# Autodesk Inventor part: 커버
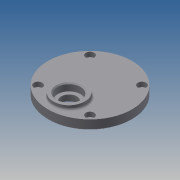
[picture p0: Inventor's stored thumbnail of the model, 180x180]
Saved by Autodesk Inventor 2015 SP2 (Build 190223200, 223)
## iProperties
Created: 2015-06
Part Number: 커버
Material: 일반
Document SubType Name: Modeling
Designer: AMC
Density: 1 g/cm^3
Appearance: 기본값
Author: AMC
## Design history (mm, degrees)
sketch "스케치1"
  geometry: C1 r 40 at (0, 0); 1 further point
  constraints: 1 centre point, 1 coincident
  dimensions: "d0" = 80 diameter of C1
extrude "돌출1" new body sketch "스케치1" distance "d1" = 9; taper "d2" = 0 deg
sketch "스케치2"
  geometry: C1 r 40 at (0, 0) reference; C2 r 15 at (0, -20); 1 further point
  constraints: 1 centre point, 1 vertical alignment
  dimensions: "d3" = 30 diameter of C2; "d4" = 20 distance of point (0, 0) C2.centre
extrude "돌출2" join sketch "스케치2" distance "d5" = 4; taper "d6" = 0 deg
sketch "스케치3"
  geometry: C1 r 14 at (0, -20); C2 r 14 at (0, 11); 1 further point
  constraints: 2 centre point, 2 vertical alignment
  dimensions: "d7" = 28 diameter of C1; "d8" = 20 distance of point (0, 0) C1.centre; "d9" = 11 distance of point (0, 0) C2.centre; "d10" = 28 diameter of C2
extrude "돌출3" join sketch "스케치3" distance "d11" = 3; taper "d12" = 0 deg
hole "구멍1" diameter "d15" = 15; stored, may be unused: countersink angle "d19" = 90 deg, drill point angle "d21" = 118 deg; dims "d13" = 10, "d14" = 10, "d16" = 6, "d17" = 22, "d18" = 7, "d20" = 8
node "작업 평면1"
sketch "스케치4"
  geometry: C1 r 14 at (0, 0) reference; C2 r 11 at (0, 0); 1 further point
  constraints: 1 centre point, 1 coincident
  dimensions: "d22" = 22 diameter of C2
extrude "돌출4" cut sketch "스케치4" distance "d23" = 7; taper "d24" = 0 deg
sketch "스케치5"
  geometry: C1 r 11 at (0, 0) reference; C2 r 9 at (0, 0); 1 further point
  constraints: 1 centre point, 1 coincident
  dimensions: "d25" = 18 diameter of C2
extrude "돌출5" cut sketch "스케치5" distance "d26" = 1; taper "d27" = 0 deg
fillet "모깎기1" dims "d28" = 1, "d29" = 0.3
chamfer "모따기1" distance "d30" = 1; stored, may be unused: second distance "d31" = 2, angle "d32" = 45 deg
sketch "스케치7"
  geometry: L1 (0, 0)-(-21.753, 0); 2 further points
  constraints: 2 end point, 1 coincident, 1 horizontal
  dimensions: "d35" = 45 deg dimension on L1.start L1.end point (-24.749, 24.749); "d36" = 35 distance of L1.start point (-24.749, 24.749)
hole "구멍2" sketch "스케치7" at (-24.749, 24.749) diameter "d37" = 4.5; stored, may be unused: countersink angle "d41" = 90 deg, drill point angle "d43" = 0 deg; dims "d38" = 6, "d39" = 8, "d40" = 4.4, "d42" = 8
fillet "모깎기2" dims "d47" = 2
chamfer "모따기2" distance "d48" = 1; stored, may be unused: second distance "d49" = 2, angle "d50" = 45 deg
node "솔리드1"
mirror "대칭1"
pattern_circular "원형 패턴1" dims angle "d45" = 360 deg
node "투영된 루프1"
node "투영된 루프2"
node "투영된 루프3"
